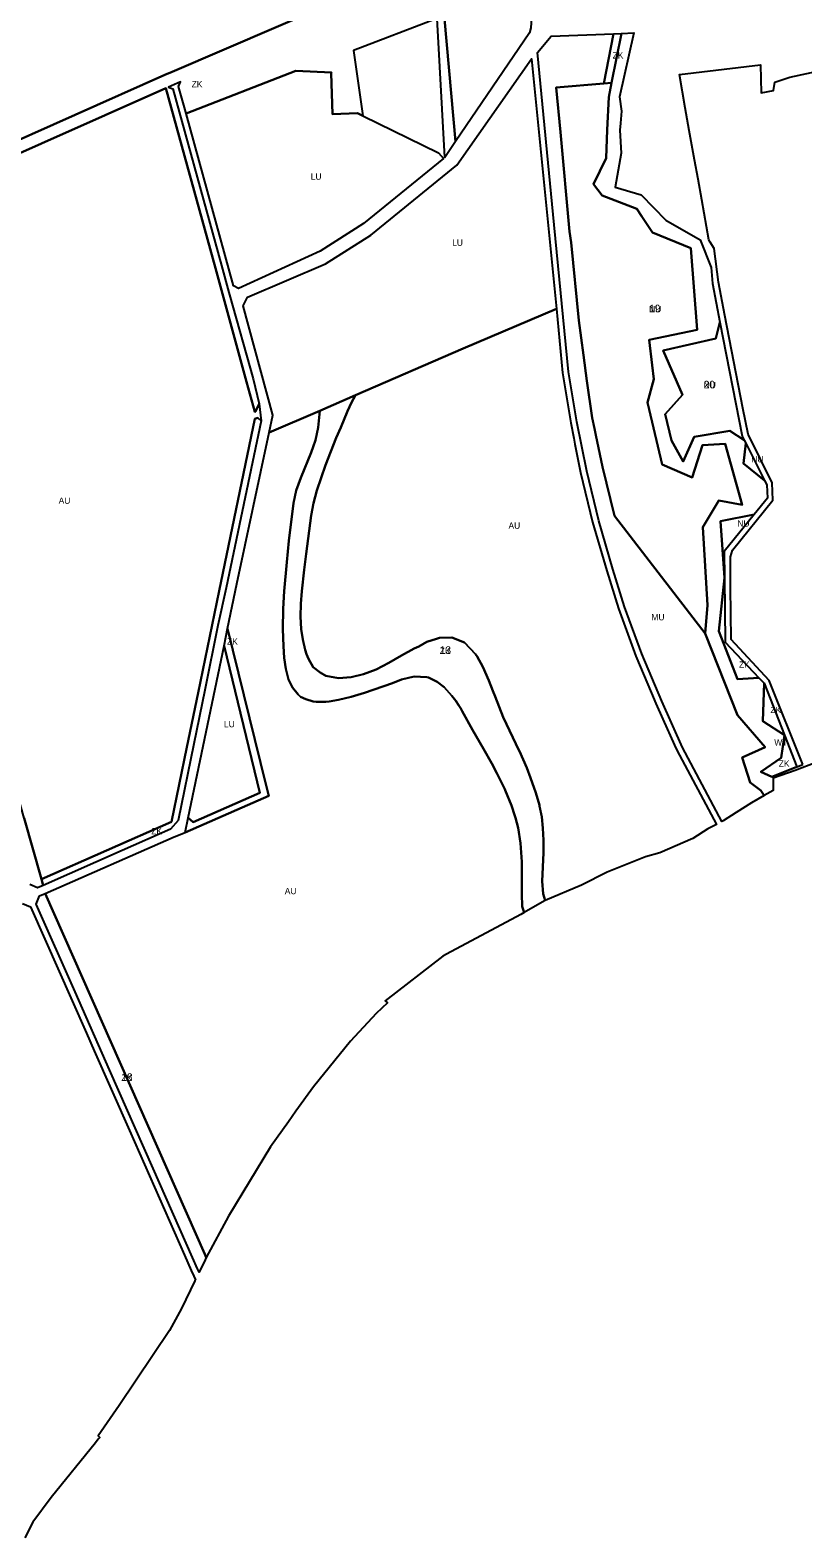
# Model space of a CAD drawing. Extents: x -522079 to -518833, y -1142398 to -1139961.
# Drawn here: x -521003 to -520390, y -1142382 to -1141186 of the extents above; entities that cross this region are included whole.
import ezdxf

# ---------------------------------------------------------------- set-up
doc = ezdxf.new("R2010")
doc.units = 0
for name, color, linetype in [('90640013', 7, 'Continuous'), ('90680023', 7, 'Continuous'), ('90710013', 7, 'Continuous'), ('90710023', 7, 'Continuous'), ('90730013', 7, 'Continuous'), ('90730023', 7, 'Continuous'), ('90750013', 7, 'Continuous'), ('90770013', 7, 'Continuous'), ('90830013', 7, 'Continuous'), ('ID_navrh', 7, 'Continuous')]:
    doc.layers.add(name, color=color, linetype=linetype)

msp = doc.modelspace()

# ---------------------------------------------------------------- linework, layer by layer
at = {"layer": '90640013'}
msp.add_lwpolyline([(-520379.93, -1141766.64), (-520396.49, -1141772.96), (-520413.8, -1141779.11), (-520413.91, -1141788.74), (-520421.03, -1141792.82), (-520423.68, -1141788.92), (-520431.99, -1141782.5), (-520438.59, -1141762.62), (-520420.15, -1141754.6), (-520442.29, -1141729.04), (-520467.83, -1141664.2), (-520465.85, -1141641.84), (-520469.63, -1141579.9), (-520457.06, -1141558.71), (-520438.57, -1141562.32), (-520451.9, -1141513.8), (-520469.99, -1141514.94), (-520478.09, -1141540.57), (-520501.99, -1141530.25), (-520512.09, -1141486.67), (-520513.39, -1141481.08), (-520508.38, -1141462.38), (-520509.69, -1141451.35), (-520512.06, -1141431.3), (-520474.23, -1141423.42), (-520479.06, -1141358.55), (-520509.58, -1141346.13), (-520517.94, -1141333.55), (-520521.95, -1141327.46), (-520549.32, -1141316.76), (-520556.25, -1141307.68), (-520546.39, -1141287.04), (-520545.37, -1141264.63), (-520544.19, -1141238.83), (-520541.94, -1141227.47), (-520534.17, -1141188.18), (-520524.27, -1141187.6), (-520535.7, -1141238.47), (-520534.05, -1141249.88), (-520534.84, -1141259.42), (-520535.3, -1141264.93), (-520534.35, -1141283.17), (-520539.2, -1141310.09), (-520518.61, -1141316.36), (-520499.06, -1141336.21), (-520471.76, -1141351.9), (-520463.1, -1141373.93), (-520462.06, -1141386.7), (-520456.11, -1141417.28), (-520459.35, -1141430.33), (-520501.13, -1141439.65), (-520485.81, -1141474.99), (-520499.43, -1141490.33), (-520494.54, -1141511.04), (-520485.33, -1141527.78), (-520476.51, -1141508.33), (-520448.25, -1141503.52), (-520436.83, -1141511), (-520435.68, -1141513.27), (-520437.33, -1141529.38), (-520420.69, -1141542.88), (-520419, -1141546.21), (-520418.4, -1141556.83), (-520428.95, -1141569.87), (-520455.53, -1141575.25), (-520452.43, -1141620.06), (-520456.84, -1141662.39), (-520442.1, -1141700.42), (-520425.12, -1141699.44), (-520421.11, -1141703.69), (-520422.16, -1141733.79), (-520405.02, -1141744.98), (-520407.65, -1141762.99), (-520423.68, -1141774.01), (-520414.86, -1141777.92), (-520395.26, -1141770.17), (-520390.37, -1141768.15)], dxfattribs=at)
at = {"layer": '90680023'}
msp.add_lwpolyline([(-520601.54, -1141117.64), (-520606.07, -1141183.78), (-520607.02, -1141187.64), (-520665.65, -1141273.94), (-520677.78, -1141138.02), (-520612.8, -1141110.04)], close=True, dxfattribs=at)
at = {"layer": '90710013'}
for points in [[(-520677.78, -1141138.02), (-520665.65, -1141273.94), (-520674.18, -1141286.49), (-520680.34, -1141176.38), (-520746.65, -1141201.66), (-520746.38, -1141203.48), (-520739.03, -1141253.62), (-520743.39, -1141251.48), (-520763.26, -1141252.34), (-520764.2, -1141219.7), (-520763.86, -1141219.18), (-520792.12, -1141217.97), (-520879.25, -1141251.61), (-520880.53, -1141246.97), (-520885.33, -1141230.38), (-520883.56, -1141226.59), (-520893.13, -1141230.74), (-520889.86, -1141232.13), (-520851.22, -1141372.34), (-520845.27, -1141393.64), (-520844.73, -1141395.54), (-520826.14, -1141462.3), (-520821.3, -1141482.16), (-520824.28, -1141488.21), (-520824.77, -1141488.43), (-520831.3, -1141464.59), (-520856.02, -1141374.46), (-520895.18, -1141231.65), (-521140.66, -1141340.91)], [(-521038.45, -1141284.46), (-520895.96, -1141221.04), (-520890.16, -1141218.54), (-520727.16, -1141148.38)]]:
    msp.add_lwpolyline(points, dxfattribs=at)
for points in [[(-520540.34, -1141188.43), (-520534.17, -1141188.18), (-520541.94, -1141227.47), (-520548.16, -1141227.97)], [(-520993.82, -1141859.25), (-520890.85, -1141813.79), (-520878.55, -1141754.38), (-520869.65, -1141711.4), (-520852.89, -1141630.48), (-520824.63, -1141494.01), (-520822.47, -1141493.04), (-520819.82, -1141495.44), (-520847.36, -1141628.04), (-520854, -1141657.98), (-520864.49, -1141709.14), (-520873.01, -1141751.95), (-520885.53, -1141812.75), (-520891.63, -1141819.53), (-520930.02, -1141836.55), (-520992.44, -1141864.11)], [(-520425.12, -1141699.44), (-520442.1, -1141700.42), (-520456.84, -1141662.39), (-520452.43, -1141620.06), (-520451.86, -1141671.07)], [(-520877.47, -1141810.66), (-520873.57, -1141813.91), (-520820.88, -1141790.77), (-520849.15, -1141674.02), (-520846.32, -1141660.34), (-520815.91, -1141783.74), (-520813.61, -1141793.09), (-520834.71, -1141802.36), (-520879.93, -1141822.22)], [(-520421.11, -1141703.69), (-520405.02, -1141744.98), (-520422.16, -1141733.79)], [(-520395.26, -1141770.17), (-520414.86, -1141777.92), (-520423.68, -1141774.01), (-520407.65, -1141762.99), (-520405.02, -1141744.98)]]:
    msp.add_lwpolyline(points, close=True, dxfattribs=at)
at = {"layer": '90710023'}
for points in [[(-520594.48, -1141876.16), (-520595.23, -1141876.48), (-520611.23, -1141885.62), (-520612.71, -1141880.76), (-520613.19, -1141870.76), (-520613.05, -1141845.33), (-520614.04, -1141830.76), (-520616.14, -1141818.42), (-520618.17, -1141810.44), (-520618.62, -1141809.07), (-520621.34, -1141800.76), (-520626.27, -1141788.54), (-520626.68, -1141787.7), (-520632.79, -1141775.07), (-520637, -1141767.42), (-520643.44, -1141755.72), (-520652.18, -1141740.76), (-520660.44, -1141725.82), (-520661.54, -1141723.82), (-520663.04, -1141721.47), (-520665.44, -1141717.71), (-520668.49, -1141713.61), (-520674.58, -1141706.85), (-520680.23, -1141702.5), (-520686.99, -1141699.26), (-520688.49, -1141698.8), (-520698.49, -1141698.33), (-520708.49, -1141700.66), (-520715.69, -1141703.56), (-520737.83, -1141711.42), (-520748.49, -1141714.63), (-520758.49, -1141717.01), (-520765.89, -1141718.16), (-520768.49, -1141718.49), (-520776.22, -1141718.49), (-520778.49, -1141718.29), (-520784.24, -1141716.51), (-520788.49, -1141714.55), (-520790.51, -1141712.79), (-520794.86, -1141707.13), (-520798.14, -1141700.76), (-520800.15, -1141692.43), (-520801.39, -1141683.67), (-520802.12, -1141674.39), (-520802.58, -1141660.76), (-520802.32, -1141644.59), (-520801.52, -1141630.76), (-520799.43, -1141607.66), (-520797.9, -1141590.76), (-520794.11, -1141560.76), (-520791.87, -1141550.76), (-520788.33, -1141540.76), (-520780.07, -1141520.76), (-520778.49, -1141516.25), (-520776.72, -1141510.76), (-520774.42, -1141500.76), (-520773.3, -1141487.53), (-520745.05, -1141475.27), (-520748.12, -1141481.13), (-520751.33, -1141487.92), (-520756.59, -1141500.76), (-520760.32, -1141508.93), (-520768.6, -1141530.76), (-520775.47, -1141550.76), (-520778.33, -1141560.76), (-520780.2, -1141570.76), (-520784.01, -1141600.98), (-520785.6, -1141613.65), (-520787.54, -1141630.76), (-520788.33, -1141640.76), (-520788.48, -1141650.77), (-520787.95, -1141660.76), (-520786.77, -1141669.05), (-520784.93, -1141677.21), (-520783.84, -1141680.76), (-520782.24, -1141684.51), (-520778.49, -1141691.03), (-520772.97, -1141695.24), (-520768.49, -1141697.8), (-520758.49, -1141699.72), (-520748.49, -1141698.92), (-520738.49, -1141696.45), (-520728.49, -1141692.76), (-520718.49, -1141687.63), (-520708.49, -1141681.73), (-520698.49, -1141676.14), (-520694.77, -1141674.48), (-520688.49, -1141670.81), (-520680.68, -1141668.57), (-520678.49, -1141667.68), (-520668.49, -1141667.34), (-520658.49, -1141671.54), (-520649.78, -1141680.76), (-520648.49, -1141682.61), (-520644.07, -1141690.76), (-520639.3, -1141701.58), (-520636.14, -1141709.65), (-520634.31, -1141714.34), (-520627.89, -1141730.76), (-520615.1, -1141757.37), (-520614.96, -1141757.69), (-520609.24, -1141770.76), (-520606.35, -1141778.69), (-520601.96, -1141790.76), (-520599.21, -1141800.48), (-520598.99, -1141801.26), (-520597.38, -1141809.66), (-520596.37, -1141818.65), (-520595.96, -1141828.23), (-520596.03, -1141838.3), (-520596.94, -1141860.76), (-520596.28, -1141870.76)], [(-520990.8, -1141870.5), (-520864.37, -1142156.71), (-520863.18, -1142159.4), (-520864.2, -1142161.29), (-520868.95, -1142171.08), (-520870.13, -1142168.42), (-520874.16, -1142159.29), (-520905.36, -1142088.65), (-520939.85, -1142010.61), (-520967.25, -1141948.55), (-520997.93, -1141879.1), (-520995.39, -1141872.52)]]:
    msp.add_lwpolyline(points, close=True, dxfattribs=at)
msp.add_lwpolyline([(-521007.52, -1141810.87), (-520993.82, -1141859.25), (-520992.44, -1141864.11), (-520997.06, -1141866.15), (-521003.04, -1141863.38)], dxfattribs=at)
at = {"layer": '90730013'}
for points in [[(-520435.68, -1141513.27), (-520420.69, -1141542.88), (-520437.33, -1141529.38)], [(-520428.95, -1141569.87), (-520452.66, -1141599.19), (-520452.43, -1141620.06), (-520455.53, -1141575.25)]]:
    msp.add_lwpolyline(points, close=True, dxfattribs=at)
at = {"layer": '90730023'}
for points in [[(-520467.83, -1141664.2), (-520539.75, -1141570.9), (-520549.23, -1141532.17), (-520554.45, -1141506.79), (-520555.49, -1141501.75), (-520557.24, -1141493.24), (-520561.66, -1141463.92), (-520564.35, -1141443.41), (-520567.96, -1141415.92), (-520573.91, -1141353.97), (-520575.29, -1141345.21), (-520582.4, -1141266.58), (-520585.84, -1141231.02), (-520548.16, -1141227.97), (-520541.94, -1141227.47), (-520544.19, -1141238.83), (-520545.37, -1141264.63), (-520546.39, -1141287.04), (-520556.25, -1141307.68), (-520549.32, -1141316.76), (-520521.95, -1141327.46), (-520517.94, -1141333.55), (-520509.58, -1141346.13), (-520479.06, -1141358.55), (-520474.23, -1141423.42), (-520512.06, -1141431.3), (-520509.69, -1141451.35), (-520508.38, -1141462.38), (-520513.39, -1141481.08), (-520512.09, -1141486.67), (-520501.99, -1141530.25), (-520478.09, -1141540.57), (-520469.99, -1141514.94), (-520451.9, -1141513.8), (-520438.57, -1141562.32), (-520457.06, -1141558.71), (-520469.63, -1141579.9), (-520465.85, -1141641.84)], [(-520456.11, -1141417.28), (-520438.53, -1141507.64), (-520436.83, -1141511), (-520448.25, -1141503.52), (-520476.51, -1141508.33), (-520485.33, -1141527.78), (-520494.54, -1141511.04), (-520499.43, -1141490.33), (-520485.81, -1141474.99), (-520501.13, -1141439.65), (-520459.35, -1141430.33)]]:
    msp.add_lwpolyline(points, close=True, dxfattribs=at)
at = {"layer": '90750013'}
for points in [[(-520727.16, -1141148.38), (-520890.16, -1141218.54), (-520895.96, -1141221.04), (-521038.45, -1141284.46), (-521081.35, -1141303.56), (-521117.38, -1141319.6), (-521143.42, -1141331.19), (-521216.29, -1141073.97), (-521190.59, -1141062.63), (-521154.28, -1141046.62), (-521111.47, -1141027.75), (-521085.77, -1141016.42), (-520964.29, -1140970.32), (-520959.78, -1140968.46), (-520892.3, -1140942.89), (-520888.93, -1140954.41), (-520885.58, -1140965.84), (-520881.52, -1140979.72), (-520872.93, -1141009.05), (-520861.45, -1141049.84), (-520847.24, -1141100.33), (-520846.14, -1141104.23), (-520733.88, -1141082.24)], [(-520993.82, -1141859.25), (-521007.52, -1141810.87), (-521017.38, -1141776.07), (-521035.75, -1141711.23), (-521066.79, -1141601.67), (-521068.18, -1141596.78), (-521074.97, -1141572.8), (-521100.48, -1141482.76), (-521140.66, -1141340.91), (-520895.18, -1141231.65), (-520856.02, -1141374.46), (-520831.3, -1141464.59), (-520824.77, -1141488.43), (-520824.28, -1141488.21), (-520821.3, -1141482.16), (-520819.82, -1141495.44), (-520822.47, -1141493.04), (-520824.63, -1141494.01), (-520852.89, -1141630.48), (-520869.65, -1141711.4), (-520878.55, -1141754.38), (-520890.85, -1141813.79)], [(-520594.48, -1141876.16), (-520596.28, -1141870.76), (-520596.94, -1141860.76), (-520596.03, -1141838.3), (-520595.96, -1141828.23), (-520596.37, -1141818.65), (-520597.38, -1141809.66), (-520598.99, -1141801.26), (-520599.21, -1141800.48), (-520601.96, -1141790.76), (-520606.35, -1141778.69), (-520609.24, -1141770.76), (-520614.96, -1141757.69), (-520615.1, -1141757.37), (-520627.89, -1141730.76), (-520634.31, -1141714.34), (-520636.14, -1141709.65), (-520639.3, -1141701.58), (-520644.07, -1141690.76), (-520648.49, -1141682.61), (-520649.78, -1141680.76), (-520658.49, -1141671.54), (-520668.49, -1141667.34), (-520678.49, -1141667.68), (-520680.68, -1141668.57), (-520688.49, -1141670.81), (-520694.77, -1141674.48), (-520698.49, -1141676.14), (-520708.49, -1141681.73), (-520718.49, -1141687.63), (-520728.49, -1141692.76), (-520738.49, -1141696.45), (-520748.49, -1141698.92), (-520758.49, -1141699.72), (-520768.49, -1141697.8), (-520772.97, -1141695.24), (-520778.49, -1141691.03), (-520782.24, -1141684.51), (-520783.84, -1141680.76), (-520784.93, -1141677.21), (-520786.77, -1141669.05), (-520787.95, -1141660.76), (-520788.48, -1141650.77), (-520788.33, -1141640.76), (-520787.54, -1141630.76), (-520785.6, -1141613.65), (-520784.01, -1141600.98), (-520780.2, -1141570.76), (-520778.33, -1141560.76), (-520775.47, -1141550.76), (-520768.6, -1141530.76), (-520760.32, -1141508.93), (-520756.59, -1141500.76), (-520751.33, -1141487.92), (-520748.12, -1141481.13), (-520745.05, -1141475.27), (-520659.49, -1141438.15), (-520585.72, -1141406.64), (-520580.93, -1141457.51), (-520574.39, -1141497.17), (-520572, -1141509.22), (-520571.03, -1141514.08), (-520569.98, -1141519.36), (-520566.58, -1141536.47), (-520557.06, -1141576.08), (-520545.85, -1141614.67), (-520536.49, -1141644.52), (-520529.1, -1141664.77), (-520528.04, -1141667.68), (-520522.71, -1141682.28), (-520510.4, -1141711.55), (-520506.95, -1141719.75), (-520501.37, -1141732.13), (-520491.98, -1141752.99), (-520490.19, -1141756.96), (-520458.87, -1141815.72), (-520465.55, -1141819.35), (-520477.66, -1141826.82), (-520503.7, -1141838.29), (-520515.18, -1141841.56), (-520545.58, -1141853.73), (-520565.76, -1141863.93)], [(-520990.8, -1141870.5), (-520888.63, -1141825.55), (-520879.93, -1141822.22), (-520834.71, -1141802.36), (-520813.61, -1141793.09), (-520815.91, -1141783.74), (-520846.32, -1141660.34), (-520838.97, -1141624.77), (-520813.35, -1141504.9), (-520773.3, -1141487.53), (-520774.42, -1141500.76), (-520776.72, -1141510.76), (-520778.49, -1141516.25), (-520780.07, -1141520.76), (-520788.33, -1141540.76), (-520791.87, -1141550.76), (-520794.11, -1141560.76), (-520797.9, -1141590.76), (-520799.43, -1141607.66), (-520801.52, -1141630.76), (-520802.32, -1141644.59), (-520802.58, -1141660.76), (-520802.12, -1141674.39), (-520801.39, -1141683.67), (-520800.15, -1141692.43), (-520798.14, -1141700.76), (-520794.86, -1141707.13), (-520790.51, -1141712.79), (-520788.49, -1141714.55), (-520784.24, -1141716.51), (-520778.49, -1141718.29), (-520776.22, -1141718.49), (-520768.49, -1141718.49), (-520765.89, -1141718.16), (-520758.49, -1141717.01), (-520748.49, -1141714.63), (-520737.83, -1141711.42), (-520715.69, -1141703.56), (-520708.49, -1141700.66), (-520698.49, -1141698.33), (-520688.49, -1141698.8), (-520686.99, -1141699.26), (-520680.23, -1141702.5), (-520674.58, -1141706.85), (-520668.49, -1141713.61), (-520665.44, -1141717.71), (-520663.04, -1141721.47), (-520661.54, -1141723.82), (-520660.44, -1141725.82), (-520652.18, -1141740.76), (-520643.44, -1141755.72), (-520637, -1141767.42), (-520632.79, -1141775.07), (-520626.68, -1141787.7), (-520626.27, -1141788.54), (-520621.34, -1141800.76), (-520618.62, -1141809.07), (-520618.17, -1141810.44), (-520616.14, -1141818.42), (-520614.04, -1141830.76), (-520613.05, -1141845.33), (-520613.19, -1141870.76), (-520612.71, -1141880.76), (-520611.23, -1141885.62), (-520613.84, -1141887.11), (-520637.23, -1141899.54), (-520669.31, -1141916.94), (-520675.72, -1141920.42), (-520721.33, -1141955.66), (-520719.53, -1141957.2), (-520728.5, -1141965.87), (-520748.85, -1141987.64), (-520778.35, -1142023.99), (-520792.36, -1142043.35), (-520798.04, -1142051.82), (-520812.28, -1142071.49), (-520845.48, -1142126.69), (-520863.18, -1142159.4), (-520864.37, -1142156.71)]]:
    msp.add_lwpolyline(points, close=True, dxfattribs=at)
for points in [[(-520390.37, -1141768.15), (-520417.08, -1141701.53), (-520447.22, -1141669.1), (-520447.6, -1141627.85), (-520447.63, -1141624.46), (-520447.82, -1141603.5), (-520446.02, -1141598.19), (-520414.26, -1141558.37), (-520414.56, -1141544.64), (-520433.82, -1141506.13), (-520437.82, -1141485.59), (-520452.14, -1141412.08), (-520457.31, -1141385.57), (-520460.62, -1141358.83), (-520463.71, -1141353.8), (-520464.8, -1141352.03), (-520470.52, -1141320.08), (-520473.45, -1141303.71), (-520476.2, -1141288.34), (-520480.37, -1141265.08), (-520483.58, -1141247.19), (-520488.14, -1141220.84), (-520423.9, -1141213.13), (-520423.33, -1141235.38), (-520413.51, -1141233.43), (-520412.54, -1141226.76), (-520400.61, -1141222.82), (-520352.78, -1141212.63)], [(-521009, -1141878.54), (-521002.46, -1141881.16), (-520958.2, -1141981.43), (-520951.97, -1141995.53), (-520924.06, -1142058.74), (-520880.4, -1142157.63), (-520875.14, -1142169.56), (-520873.11, -1142174.16), (-520871.84, -1142177.03), (-520872.25, -1142177.87), (-520882.99, -1142199.96), (-520892.25, -1142217.33), (-520932.3, -1142276.81), (-520949.04, -1142300.8), (-520947.69, -1142302.08), (-520948.83, -1142303.49), (-520951.1, -1142306.31), (-520986.1, -1142349.82), (-521000.81, -1142369.28), (-521007.1, -1142381.81)]]:
    msp.add_lwpolyline(points, dxfattribs=at)
at = {"layer": '90770013'}
for points in [[(-520675.31, -1141287.41), (-520738.6, -1141338.95), (-520773.04, -1141360.9), (-520837.57, -1141390.54), (-520841.7, -1141388.53), (-520879.25, -1141251.61), (-520792.12, -1141217.97), (-520763.86, -1141219.18), (-520764.2, -1141219.7), (-520763.26, -1141252.34), (-520743.39, -1141251.48), (-520739.03, -1141253.62), (-520679.28, -1141282.96)], [(-520773.3, -1141487.53), (-520813.35, -1141504.9), (-520810.51, -1141490.93), (-520834.09, -1141404.31), (-520830.45, -1141397.51), (-520768.7, -1141371.01), (-520732.72, -1141348.25), (-520664.52, -1141292.81), (-520605.35, -1141208.42), (-520585.72, -1141406.64), (-520659.49, -1141438.15), (-520745.05, -1141475.27)], [(-520877.47, -1141810.66), (-520849.15, -1141674.02), (-520820.88, -1141790.77), (-520873.57, -1141813.91)]]:
    msp.add_lwpolyline(points, close=True, dxfattribs=at)
at = {"layer": '90830013'}
msp.add_lwpolyline([(-520540.34, -1141188.43), (-520548.16, -1141227.97), (-520585.84, -1141231.02), (-520582.4, -1141266.58), (-520575.29, -1141345.21), (-520573.91, -1141353.97), (-520567.96, -1141415.92), (-520564.35, -1141443.41), (-520561.66, -1141463.92), (-520557.24, -1141493.24), (-520555.49, -1141501.75), (-520554.45, -1141506.79), (-520549.23, -1141532.17), (-520539.75, -1141570.9), (-520467.83, -1141664.2), (-520442.29, -1141729.04), (-520420.15, -1141754.6), (-520438.59, -1141762.62), (-520431.99, -1141782.5), (-520423.68, -1141788.92), (-520421.03, -1141792.82), (-520431, -1141798.52), (-520443.29, -1141806.35), (-520453.46, -1141812.83), (-520454.47, -1141813.35), (-520485.78, -1141754.61), (-520502.23, -1141718.09), (-520518.1, -1141680.34), (-520531.72, -1141643.02), (-520541.05, -1141613.27), (-520552.2, -1141574.91), (-520561.68, -1141535.49), (-520569.46, -1141496.36), (-520576, -1141456.7), (-520587.35, -1141340.09), (-520600.66, -1141203.4), (-520589.77, -1141190.43)], close=True, dxfattribs=at)

# ---------------------------------------------------------------- texts
at = {"layer": '90640013'}
msp.add_text('WT', height=5, rotation=360, dxfattribs=at).set_placement((-520413.025, -1141753.219))
at = {"layer": '90710013'}
for rotation, p in [(0, (-520541.165, -1141208.076)), (0, (-520874.83, -1141230.922)), (0, (-520440.98, -1141691.484)), (360, (-520416.097, -1141727.487)), (0, (-520409.47, -1141770.015)), (0, (-520906.82, -1141823.552))]:
    msp.add_text('ZK', height=5, rotation=rotation, dxfattribs=at).set_placement(p)
msp.add_text('ZK', height=5, dxfattribs=at).set_placement((-520846.77, -1141673.182))
at = {"layer": '90710023'}
for p in [(-520678.134, -1141680.445), (-520930.555, -1142019.262)]:
    msp.add_text('ZK', height=5, rotation=0, dxfattribs=at).set_placement(p)
at = {"layer": '90730013'}
for p in [(-520431.233, -1141528.51), (-520442.24, -1141579.432)]:
    msp.add_text('NU', height=5, rotation=0, dxfattribs=at).set_placement(p)
at = {"layer": '90730023'}
for p in [(-520512.205, -1141409.418), (-520468.98, -1141469.763)]:
    msp.add_text('NU', height=5, rotation=360, dxfattribs=at).set_placement(p)
at = {"layer": '90750013'}
for rotation, p in [(360, (-520980.24, -1141561.382)), (360, (-520623.675, -1141581.191)), (0, (-520801.015, -1141871.124))]:
    msp.add_text('AU', height=5, rotation=rotation, dxfattribs=at).set_placement(p)
at = {"layer": '90770013'}
for rotation, p in [(0, (-520780.404, -1141304.255)), (360, (-520668.342, -1141356.66)), (360, (-520849.175, -1141738.669))]:
    msp.add_text('LU', height=5, rotation=rotation, dxfattribs=at).set_placement(p)
at = {"layer": '90830013'}
msp.add_text('MU', height=5, rotation=0, dxfattribs=at).set_placement((-520510.405, -1141653.806))
at = {"layer": 'ID_navrh'}
for s, rotation, p in [('19', 0, (-520512.205, -1141409.418)), ('20', 360, (-520468.98, -1141469.763)), ('13', 360, (-520678.134, -1141680.445)), ('18', 0, (-520930.555, -1142019.262))]:
    msp.add_text(s, height=6, rotation=rotation, dxfattribs=at).set_placement(p)

doc.saveas('drawing.dxf')
